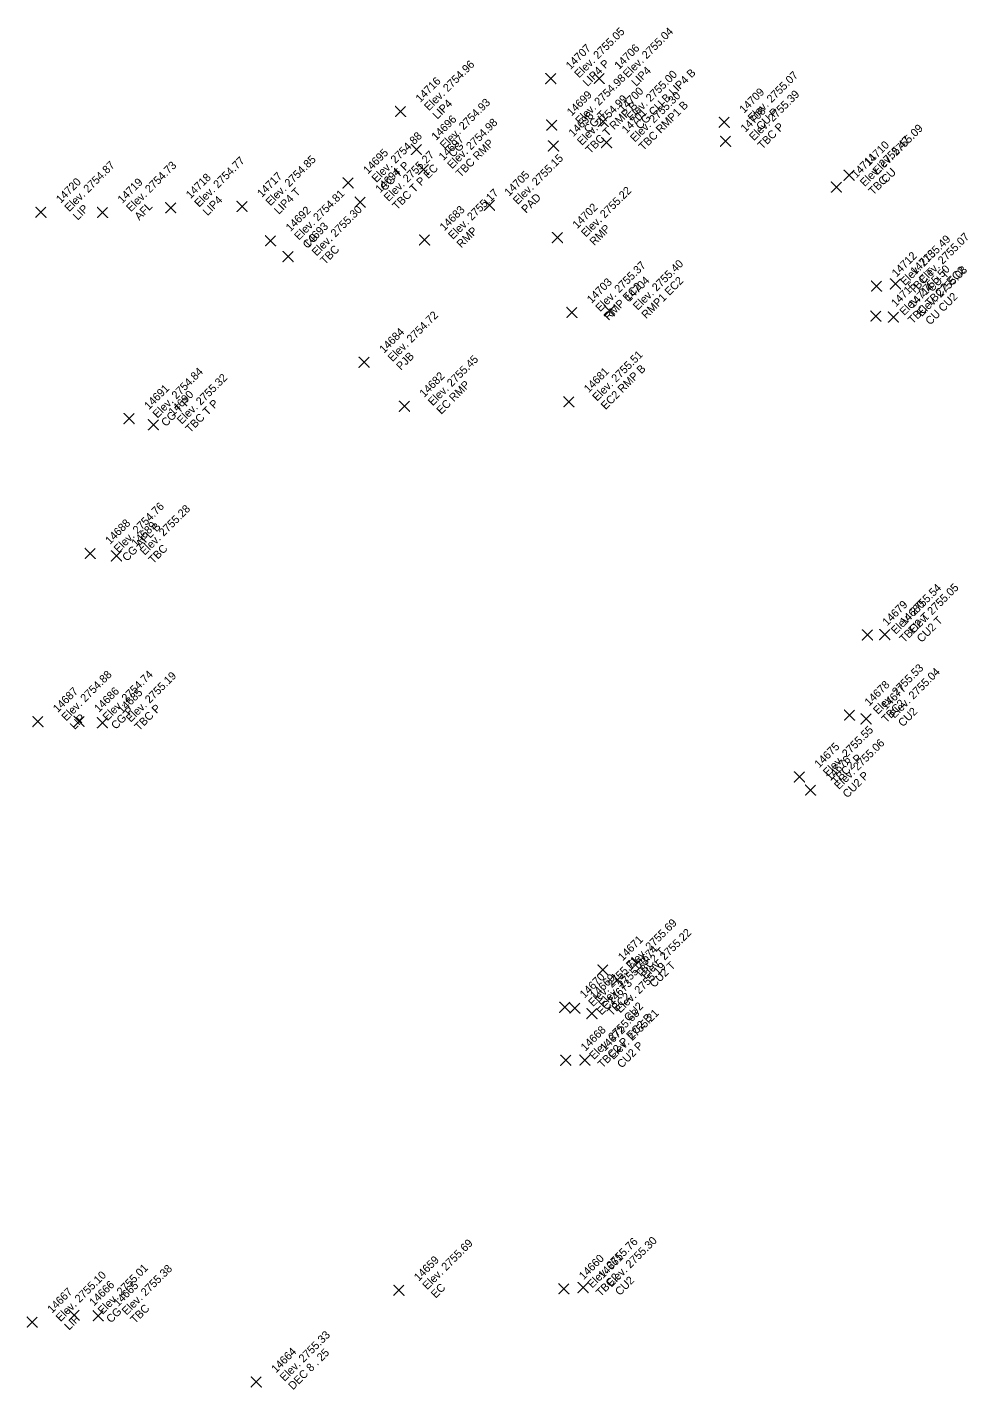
# Model space of a CAD drawing. Extents: x 2493999 to 2503109, y 700767 to 706646.
# Drawn here: x 2502323.92 to 2502352.13, y 703711.25 to 703752.11 of the extents above; entities that cross this region are included whole.
import ezdxf

# ---------------------------------------------------------------- set-up
doc = ezdxf.new("R2010")
doc.units = 0
doc.layers.add('ALG_CL_BLUE_Horiz', color=7, linetype='Continuous')
doc.layers.add('DES_SURFACE_Existing-Ground', color=7, linetype='Continuous')

msp = doc.modelspace()

# ---------------------------------------------------------------- linework, layer by layer
at = {"layer": 'ALG_CL_BLUE_Horiz'}
for points in [[(2502339.621, 703750.569), (2502339.471, 703750.719), (2502339.621, 703750.569), (2502339.471, 703750.419), (2502339.621, 703750.569), (2502339.771, 703750.419), (2502339.621, 703750.569), (2502339.771, 703750.719)], [(2502341.077, 703750.573), (2502340.927, 703750.723), (2502341.077, 703750.573), (2502340.927, 703750.423), (2502341.077, 703750.573), (2502341.227, 703750.423), (2502341.077, 703750.573), (2502341.227, 703750.723)], [(2502335.117, 703749.585), (2502334.967, 703749.735), (2502335.117, 703749.585), (2502334.967, 703749.435), (2502335.117, 703749.585), (2502335.267, 703749.435), (2502335.117, 703749.585), (2502335.267, 703749.735)], [(2502341.196, 703749.285), (2502341.046, 703749.435), (2502341.196, 703749.285), (2502341.046, 703749.135), (2502341.196, 703749.285), (2502341.346, 703749.135), (2502341.196, 703749.285), (2502341.346, 703749.435)], [(2502339.651, 703749.174), (2502339.501, 703749.324), (2502339.651, 703749.174), (2502339.501, 703749.024), (2502339.651, 703749.174), (2502339.801, 703749.024), (2502339.651, 703749.174), (2502339.801, 703749.324)], [(2502344.822, 703749.257), (2502344.672, 703749.407), (2502344.822, 703749.257), (2502344.672, 703749.107), (2502344.822, 703749.257), (2502344.972, 703749.107), (2502344.822, 703749.257), (2502344.972, 703749.407)], [(2502339.703, 703748.551), (2502339.553, 703748.701), (2502339.703, 703748.551), (2502339.553, 703748.401), (2502339.703, 703748.551), (2502339.853, 703748.401), (2502339.703, 703748.551), (2502339.853, 703748.701)], [(2502341.297, 703748.647), (2502341.147, 703748.797), (2502341.297, 703748.647), (2502341.147, 703748.497), (2502341.297, 703748.647), (2502341.447, 703748.497), (2502341.297, 703748.647), (2502341.447, 703748.797)], [(2502344.862, 703748.689), (2502344.712, 703748.839), (2502344.862, 703748.689), (2502344.712, 703748.539), (2502344.862, 703748.689), (2502345.012, 703748.539), (2502344.862, 703748.689), (2502345.012, 703748.839)], [(2502335.591, 703748.442), (2502335.441, 703748.592), (2502335.591, 703748.442), (2502335.441, 703748.292), (2502335.591, 703748.442), (2502335.741, 703748.292), (2502335.591, 703748.442), (2502335.741, 703748.592)], [(2502335.808, 703747.843), (2502335.658, 703747.993), (2502335.808, 703747.843), (2502335.658, 703747.693), (2502335.808, 703747.843), (2502335.958, 703747.693), (2502335.808, 703747.843), (2502335.958, 703747.993)], [(2502348.566, 703747.668), (2502348.416, 703747.818), (2502348.566, 703747.668), (2502348.416, 703747.518), (2502348.566, 703747.668), (2502348.716, 703747.518), (2502348.566, 703747.668), (2502348.716, 703747.818)], [(2502333.543, 703747.438), (2502333.393, 703747.588), (2502333.543, 703747.438), (2502333.393, 703747.288), (2502333.543, 703747.438), (2502333.693, 703747.288), (2502333.543, 703747.438), (2502333.693, 703747.588)], [(2502348.189, 703747.313), (2502348.039, 703747.463), (2502348.189, 703747.313), (2502348.039, 703747.163), (2502348.189, 703747.313), (2502348.339, 703747.163), (2502348.189, 703747.313), (2502348.339, 703747.463)], [(2502333.91, 703746.867), (2502333.76, 703747.017), (2502333.91, 703746.867), (2502333.76, 703746.717), (2502333.91, 703746.867), (2502334.06, 703746.717), (2502333.91, 703746.867), (2502334.06, 703747.017)], [(2502324.331, 703746.561), (2502324.181, 703746.711), (2502324.331, 703746.561), (2502324.181, 703746.411), (2502324.331, 703746.561), (2502324.481, 703746.411), (2502324.331, 703746.561), (2502324.481, 703746.711)], [(2502326.18, 703746.555), (2502326.03, 703746.705), (2502326.18, 703746.555), (2502326.03, 703746.405), (2502326.18, 703746.555), (2502326.33, 703746.405), (2502326.18, 703746.555), (2502326.33, 703746.705)], [(2502328.227, 703746.695), (2502328.077, 703746.845), (2502328.227, 703746.695), (2502328.077, 703746.545), (2502328.227, 703746.695), (2502328.377, 703746.545), (2502328.227, 703746.695), (2502328.377, 703746.845)], [(2502330.362, 703746.734), (2502330.212, 703746.884), (2502330.362, 703746.734), (2502330.212, 703746.584), (2502330.362, 703746.734), (2502330.512, 703746.584), (2502330.362, 703746.734), (2502330.512, 703746.884)], [(2502337.779, 703746.771), (2502337.629, 703746.921), (2502337.779, 703746.771), (2502337.629, 703746.621), (2502337.779, 703746.771), (2502337.929, 703746.621), (2502337.779, 703746.771), (2502337.929, 703746.921)], [(2502331.221, 703745.707), (2502331.071, 703745.857), (2502331.221, 703745.707), (2502331.071, 703745.557), (2502331.221, 703745.707), (2502331.371, 703745.557), (2502331.221, 703745.707), (2502331.371, 703745.857)], [(2502335.837, 703745.728), (2502335.687, 703745.878), (2502335.837, 703745.728), (2502335.687, 703745.578), (2502335.837, 703745.728), (2502335.987, 703745.578), (2502335.837, 703745.728), (2502335.987, 703745.878)], [(2502339.822, 703745.799), (2502339.672, 703745.949), (2502339.822, 703745.799), (2502339.672, 703745.649), (2502339.822, 703745.799), (2502339.972, 703745.649), (2502339.822, 703745.799), (2502339.972, 703745.949)], [(2502331.745, 703745.229), (2502331.595, 703745.379), (2502331.745, 703745.229), (2502331.595, 703745.079), (2502331.745, 703745.229), (2502331.895, 703745.079), (2502331.745, 703745.229), (2502331.895, 703745.379)], [(2502349.954, 703744.412), (2502349.804, 703744.562), (2502349.954, 703744.412), (2502349.804, 703744.262), (2502349.954, 703744.412), (2502350.104, 703744.262), (2502349.954, 703744.412), (2502350.104, 703744.562)], [(2502349.394, 703744.345), (2502349.244, 703744.495), (2502349.394, 703744.345), (2502349.244, 703744.195), (2502349.394, 703744.345), (2502349.544, 703744.195), (2502349.394, 703744.345), (2502349.544, 703744.495)], [(2502340.253, 703743.557), (2502340.103, 703743.707), (2502340.253, 703743.557), (2502340.103, 703743.407), (2502340.253, 703743.557), (2502340.403, 703743.407), (2502340.253, 703743.557), (2502340.403, 703743.707)], [(2502341.38, 703743.606), (2502341.23, 703743.756), (2502341.38, 703743.606), (2502341.23, 703743.456), (2502341.38, 703743.606), (2502341.53, 703743.456), (2502341.38, 703743.606), (2502341.53, 703743.756)], [(2502349.373, 703743.447), (2502349.223, 703743.597), (2502349.373, 703743.447), (2502349.223, 703743.297), (2502349.373, 703743.447), (2502349.523, 703743.297), (2502349.373, 703743.447), (2502349.523, 703743.597)], [(2502349.894, 703743.418), (2502349.744, 703743.568), (2502349.894, 703743.418), (2502349.744, 703743.268), (2502349.894, 703743.418), (2502350.044, 703743.268), (2502349.894, 703743.418), (2502350.044, 703743.568)], [(2502334.025, 703742.062), (2502333.875, 703742.212), (2502334.025, 703742.062), (2502333.875, 703741.912), (2502334.025, 703742.062), (2502334.175, 703741.912), (2502334.025, 703742.062), (2502334.175, 703742.212)], [(2502335.232, 703740.74), (2502335.082, 703740.89), (2502335.232, 703740.74), (2502335.082, 703740.59), (2502335.232, 703740.74), (2502335.382, 703740.59), (2502335.232, 703740.74), (2502335.382, 703740.89)], [(2502340.163, 703740.877), (2502340.013, 703741.027), (2502340.163, 703740.877), (2502340.013, 703740.727), (2502340.163, 703740.877), (2502340.313, 703740.727), (2502340.163, 703740.877), (2502340.313, 703741.027)], [(2502326.976, 703740.37), (2502326.826, 703740.52), (2502326.976, 703740.37), (2502326.826, 703740.22), (2502326.976, 703740.37), (2502327.126, 703740.22), (2502326.976, 703740.37), (2502327.126, 703740.52)], [(2502327.705, 703740.187), (2502327.555, 703740.337), (2502327.705, 703740.187), (2502327.555, 703740.037), (2502327.705, 703740.187), (2502327.855, 703740.037), (2502327.705, 703740.187), (2502327.855, 703740.337)], [(2502325.81, 703736.329), (2502325.66, 703736.479), (2502325.81, 703736.329), (2502325.66, 703736.179), (2502325.81, 703736.329), (2502325.96, 703736.179), (2502325.81, 703736.329), (2502325.96, 703736.479)], [(2502326.594, 703736.256), (2502326.444, 703736.406), (2502326.594, 703736.256), (2502326.444, 703736.106), (2502326.594, 703736.256), (2502326.744, 703736.106), (2502326.594, 703736.256), (2502326.744, 703736.406)], [(2502349.116, 703733.885), (2502348.966, 703734.035), (2502349.116, 703733.885), (2502348.966, 703733.735), (2502349.116, 703733.885), (2502349.266, 703733.735), (2502349.116, 703733.885), (2502349.266, 703734.035)], [(2502349.637, 703733.896), (2502349.487, 703734.046), (2502349.637, 703733.896), (2502349.487, 703733.746), (2502349.637, 703733.896), (2502349.787, 703733.746), (2502349.637, 703733.896), (2502349.787, 703734.046)], [(2502325.476, 703731.289), (2502325.326, 703731.439), (2502325.476, 703731.289), (2502325.326, 703731.139), (2502325.476, 703731.289), (2502325.626, 703731.139), (2502325.476, 703731.289), (2502325.626, 703731.439)], [(2502348.58, 703731.482), (2502348.43, 703731.632), (2502348.58, 703731.482), (2502348.43, 703731.332), (2502348.58, 703731.482), (2502348.73, 703731.332), (2502348.58, 703731.482), (2502348.73, 703731.632)], [(2502349.078, 703731.367), (2502348.928, 703731.517), (2502349.078, 703731.367), (2502348.928, 703731.217), (2502349.078, 703731.367), (2502349.228, 703731.217), (2502349.078, 703731.367), (2502349.228, 703731.517)], [(2502324.24, 703731.286), (2502324.09, 703731.436), (2502324.24, 703731.286), (2502324.09, 703731.136), (2502324.24, 703731.286), (2502324.39, 703731.136), (2502324.24, 703731.286), (2502324.39, 703731.436)], [(2502326.176, 703731.249), (2502326.026, 703731.399), (2502326.176, 703731.249), (2502326.026, 703731.099), (2502326.176, 703731.249), (2502326.326, 703731.099), (2502326.176, 703731.249), (2502326.326, 703731.399)], [(2502347.077, 703729.626), (2502346.927, 703729.776), (2502347.077, 703729.626), (2502346.927, 703729.476), (2502347.077, 703729.626), (2502347.227, 703729.476), (2502347.077, 703729.626), (2502347.227, 703729.776)], [(2502347.413, 703729.233), (2502347.263, 703729.383), (2502347.413, 703729.233), (2502347.263, 703729.083), (2502347.413, 703729.233), (2502347.563, 703729.083), (2502347.413, 703729.233), (2502347.563, 703729.383)], [(2502341.185, 703723.838), (2502341.035, 703723.988), (2502341.185, 703723.838), (2502341.035, 703723.688), (2502341.185, 703723.838), (2502341.335, 703723.688), (2502341.185, 703723.838), (2502341.335, 703723.988)], [(2502341.62, 703723.546), (2502341.47, 703723.696), (2502341.62, 703723.546), (2502341.47, 703723.396), (2502341.62, 703723.546), (2502341.77, 703723.396), (2502341.62, 703723.546), (2502341.77, 703723.696)], [(2502340.04, 703722.72), (2502339.89, 703722.87), (2502340.04, 703722.72), (2502339.89, 703722.57), (2502340.04, 703722.72), (2502340.19, 703722.57), (2502340.04, 703722.72), (2502340.19, 703722.87)], [(2502340.347, 703722.692), (2502340.197, 703722.842), (2502340.347, 703722.692), (2502340.197, 703722.542), (2502340.347, 703722.692), (2502340.497, 703722.542), (2502340.347, 703722.692), (2502340.497, 703722.842)], [(2502340.856, 703722.531), (2502340.706, 703722.681), (2502340.856, 703722.531), (2502340.706, 703722.381), (2502340.856, 703722.531), (2502341.006, 703722.381), (2502340.856, 703722.531), (2502341.006, 703722.681)], [(2502340.068, 703721.131), (2502339.918, 703721.281), (2502340.068, 703721.131), (2502339.918, 703720.981), (2502340.068, 703721.131), (2502340.218, 703720.981), (2502340.068, 703721.131), (2502340.218, 703721.281)], [(2502340.647, 703721.132), (2502340.497, 703721.282), (2502340.647, 703721.132), (2502340.497, 703720.982), (2502340.647, 703721.132), (2502340.797, 703720.982), (2502340.647, 703721.132), (2502340.797, 703721.282)], [(2502335.066, 703714.233), (2502334.916, 703714.383), (2502335.066, 703714.233), (2502334.916, 703714.083), (2502335.066, 703714.233), (2502335.216, 703714.083), (2502335.066, 703714.233), (2502335.216, 703714.383)], [(2502340.015, 703714.278), (2502339.865, 703714.428), (2502340.015, 703714.278), (2502339.865, 703714.128), (2502340.015, 703714.278), (2502340.165, 703714.128), (2502340.015, 703714.278), (2502340.165, 703714.428)], [(2502340.589, 703714.31), (2502340.439, 703714.46), (2502340.589, 703714.31), (2502340.439, 703714.16), (2502340.589, 703714.31), (2502340.739, 703714.16), (2502340.589, 703714.31), (2502340.739, 703714.46)], [(2502325.33, 703713.489), (2502325.18, 703713.639), (2502325.33, 703713.489), (2502325.18, 703713.339), (2502325.33, 703713.489), (2502325.48, 703713.339), (2502325.33, 703713.489), (2502325.48, 703713.639)], [(2502326.053, 703713.469), (2502325.903, 703713.619), (2502326.053, 703713.469), (2502325.903, 703713.319), (2502326.053, 703713.469), (2502326.203, 703713.319), (2502326.053, 703713.469), (2502326.203, 703713.619)], [(2502324.072, 703713.275), (2502323.922, 703713.425), (2502324.072, 703713.275), (2502323.922, 703713.125), (2502324.072, 703713.275), (2502324.222, 703713.125), (2502324.072, 703713.275), (2502324.222, 703713.425)], [(2502330.787, 703711.484), (2502330.637, 703711.634), (2502330.787, 703711.484), (2502330.637, 703711.334), (2502330.787, 703711.484), (2502330.937, 703711.334), (2502330.787, 703711.484), (2502330.937, 703711.634)]]:
    msp.add_lwpolyline(points, dxfattribs=at)

# ---------------------------------------------------------------- texts
at = {"layer": 'DES_SURFACE_Existing-Ground'}
for s, p in [('Elev. 2755.05', (2502340.47, 703750.569)), ('Elev. 2755.04', (2502341.926, 703750.573)), ('14707', (2502340.215, 703750.824)), ('14706', (2502341.671, 703750.828)), ('Elev. 2754.96', (2502335.966, 703749.585)), ('LIP4 P', (2502340.724, 703750.314)), ('Elev. 2754.98', (2502340.5, 703749.174)), ('Elev. 2755.00', (2502342.045, 703749.285)), ('LIP4', (2502342.18, 703750.318)), ('CG CU B LIP4 B', (2502342.299, 703749.03)), ('Elev. 2755.07', (2502345.671, 703749.257)), ('14716', (2502335.711, 703749.84)), ('14700', (2502341.79, 703749.54)), ('14709', (2502345.416, 703749.512)), ('LIP4', (2502336.22, 703749.33)), ('Elev. 2754.93', (2502336.44, 703748.442)), ('14699', (2502340.245, 703749.429)), ('Elev. 2754.99', (2502340.552, 703748.551)), ('TBC T RMP B', (2502340.806, 703748.296)), ('Elev. 2755.30', (2502342.146, 703748.647)), ('TBC RMP1 B', (2502342.4, 703748.392)), ('Elev. 2755.39', (2502345.711, 703748.689)), ('14696', (2502336.185, 703748.697)), ('14698', (2502340.297, 703748.806)), ('CG T', (2502340.754, 703748.919)), ('14701', (2502341.891, 703748.902)), ('14708', (2502345.456, 703748.944)), ('CU P', (2502345.925, 703749.002)), ('Elev. 2754.98', (2502336.657, 703747.843)), ('TBC P', (2502345.965, 703748.434)), ('Elev. 2755.09', (2502349.415, 703747.668)), ('Elev. 2754.88', (2502334.392, 703747.438)), ('14697', (2502336.402, 703748.098)), ('CG', (2502336.694, 703748.187)), ('TBC RMP', (2502336.911, 703747.588)), ('Elev. 2755.47', (2502349.038, 703747.313)), ('14710', (2502349.16, 703747.923)), ('Elev. 2754.77', (2502329.076, 703746.695)), ('Elev. 2754.85', (2502331.211, 703746.734)), ('14695', (2502334.137, 703747.693)), ('Elev. 2755.27', (2502334.759, 703746.867)), ('Elev. 2755.15', (2502338.628, 703746.771)), ('14711', (2502348.783, 703747.568)), ('Elev. 2754.87', (2502325.18, 703746.561)), ('Elev. 2754.73', (2502327.029, 703746.555)), ('14694', (2502334.504, 703747.122)), ('CG T P', (2502334.646, 703747.183)), ('TBC T P EC', (2502335.013, 703746.612)), ('14705', (2502338.373, 703747.026)), ('CU', (2502349.669, 703747.413)), ('14720', (2502324.925, 703746.816)), ('14719', (2502326.774, 703746.81)), ('14718', (2502328.821, 703746.95)), ('14717', (2502330.956, 703746.989)), ('TBC', (2502349.292, 703747.058)), ('LIP4', (2502329.33, 703746.44)), ('LIP4 T', (2502331.465, 703746.479)), ('Elev. 2754.81', (2502332.07, 703745.707)), ('Elev. 2755.17', (2502336.686, 703745.728)), ('PAD', (2502338.882, 703746.516)), ('Elev. 2755.22', (2502340.671, 703745.799)), ('LIP', (2502325.434, 703746.306)), ('AFL', (2502327.283, 703746.3)), ('14692', (2502331.815, 703745.962)), ('Elev. 2755.30', (2502332.594, 703745.229)), ('14683', (2502336.431, 703745.983)), ('14702', (2502340.416, 703746.054)), ('14693', (2502332.339, 703745.484)), ('RMP', (2502340.925, 703745.544)), ('CG', (2502332.324, 703745.452)), ('RMP', (2502336.94, 703745.473)), ('Elev. 2755.49', (2502350.243, 703744.345)), ('Elev. 2755.07', (2502350.803, 703744.412)), ('TBC', (2502332.848, 703744.974)), ('14712', (2502349.988, 703744.6)), ('14713', (2502350.548, 703744.667)), ('Elev. 2755.37', (2502341.102, 703743.557)), ('Elev. 2755.40', (2502342.229, 703743.606)), ('Elev. 2755.50', (2502350.222, 703743.447)), ('TBC TBC2 EC2', (2502350.476, 703743.192)), ('Elev. 2755.08', (2502350.743, 703743.418)), ('14703', (2502340.847, 703743.812)), ('14704', (2502341.974, 703743.861)), ('RMP1 EC2', (2502342.483, 703743.351)), ('TBC T', (2502350.497, 703744.09)), ('CU T', (2502351.057, 703744.157)), ('RMP EC2', (2502341.356, 703743.302)), ('14715', (2502349.967, 703743.702)), ('14714', (2502350.488, 703743.673)), ('CU CU2', (2502350.997, 703743.163)), ('Elev. 2754.72', (2502334.874, 703742.062)), ('14684', (2502334.619, 703742.317)), ('PJB', (2502335.128, 703741.807)), ('Elev. 2755.45', (2502336.081, 703740.74)), ('Elev. 2755.51', (2502341.012, 703740.877)), ('Elev. 2754.84', (2502327.825, 703740.37)), ('Elev. 2755.32', (2502328.554, 703740.187)), ('14682', (2502335.826, 703740.995)), ('14681', (2502340.757, 703741.132)), ('EC2 RMP B', (2502341.266, 703740.622)), ('14691', (2502327.57, 703740.625)), ('EC RMP', (2502336.335, 703740.485)), ('CG T P', (2502328.079, 703740.115)), ('14690', (2502328.299, 703740.442)), ('TBC T P', (2502328.808, 703739.932)), ('Elev. 2754.76', (2502326.659, 703736.329)), ('Elev. 2755.28', (2502327.443, 703736.256)), ('14688', (2502326.404, 703736.584)), ('CG AFL B', (2502326.913, 703736.074)), ('14689', (2502327.188, 703736.511)), ('TBC', (2502327.697, 703736.001)), ('Elev. 2755.54', (2502349.965, 703733.885)), ('Elev. 2755.05', (2502350.486, 703733.896)), ('14679', (2502349.71, 703734.14)), ('14680', (2502350.231, 703734.151)), ('TBC2 T', (2502350.219, 703733.63)), ('CU2 T', (2502350.74, 703733.641)), ('Elev. 2754.88', (2502325.089, 703731.286)), ('Elev. 2754.74', (2502326.325, 703731.289)), ('Elev. 2755.19', (2502327.025, 703731.249)), ('Elev. 2755.53', (2502349.429, 703731.482)), ('Elev. 2755.04', (2502349.927, 703731.367)), ('14687', (2502324.834, 703731.541)), ('14686', (2502326.07, 703731.544)), ('14685', (2502326.77, 703731.504)), ('14678', (2502349.174, 703731.737)), ('14677', (2502349.672, 703731.622)), ('TBC2', (2502349.683, 703731.227)), ('LIP', (2502325.343, 703731.031)), ('CG P', (2502326.579, 703731.034)), ('TBC P', (2502327.279, 703730.994)), ('CU2', (2502350.181, 703731.112)), ('Elev. 2755.55', (2502347.926, 703729.626)), ('14675', (2502347.671, 703729.881)), ('Elev. 2755.06', (2502348.262, 703729.233)), ('14676', (2502348.007, 703729.488)), ('TBC2 P', (2502348.18, 703729.371)), ('CU2 P', (2502348.516, 703728.978)), ('Elev. 2755.69', (2502342.034, 703723.838)), ('Elev. 2755.22', (2502342.469, 703723.546)), ('14671', (2502341.779, 703724.093)), ('14674', (2502342.214, 703723.801)), ('TBC2 T', (2502342.288, 703723.583)), ('Elev. 2755.71', (2502340.889, 703722.72)), ('Elev. 2755.73', (2502341.196, 703722.692)), ('CU2 T', (2502342.723, 703723.291)), ('14670', (2502340.634, 703722.975)), ('14669', (2502340.941, 703722.947)), ('Elev. 2755.19', (2502341.705, 703722.531)), ('14673', (2502341.45, 703722.786)), ('EC2', (2502341.143, 703722.465)), ('TBC2', (2502341.45, 703722.437)), ('CU2', (2502341.959, 703722.276)), ('Elev. 2755.68', (2502340.917, 703721.131)), ('TBC2 P EC2 B', (2502341.171, 703720.876)), ('Elev. 2755.21', (2502341.496, 703721.132)), ('14668', (2502340.662, 703721.386)), ('14672', (2502341.241, 703721.387)), ('CU2 P', (2502341.75, 703720.877)), ('Elev. 2755.69', (2502335.915, 703714.233)), ('Elev. 2755.76', (2502340.864, 703714.278)), ('Elev. 2755.30', (2502341.438, 703714.31)), ('14659', (2502335.66, 703714.488)), ('14660', (2502340.609, 703714.533)), ('14661', (2502341.183, 703714.565)), ('Elev. 2755.10', (2502324.921, 703713.275)), ('Elev. 2755.01', (2502326.179, 703713.489)), ('Elev. 2755.38', (2502326.902, 703713.469)), ('TBC2', (2502341.118, 703714.023)), ('14667', (2502324.666, 703713.53)), ('14666', (2502325.924, 703713.744)), ('14665', (2502326.647, 703713.724)), ('EC', (2502336.169, 703713.978)), ('CU2', (2502341.692, 703714.055)), ('LIP', (2502325.175, 703713.02)), ('CG', (2502326.433, 703713.234)), ('TBC', (2502327.156, 703713.214)), ('Elev. 2755.33', (2502331.636, 703711.484)), ('14664', (2502331.381, 703711.739)), ('DEC 8 . 25', (2502331.89, 703711.229))]:
    msp.add_text(s, height=0.24, rotation=45, dxfattribs=at).set_placement(p)

doc.saveas('drawing.dxf')
